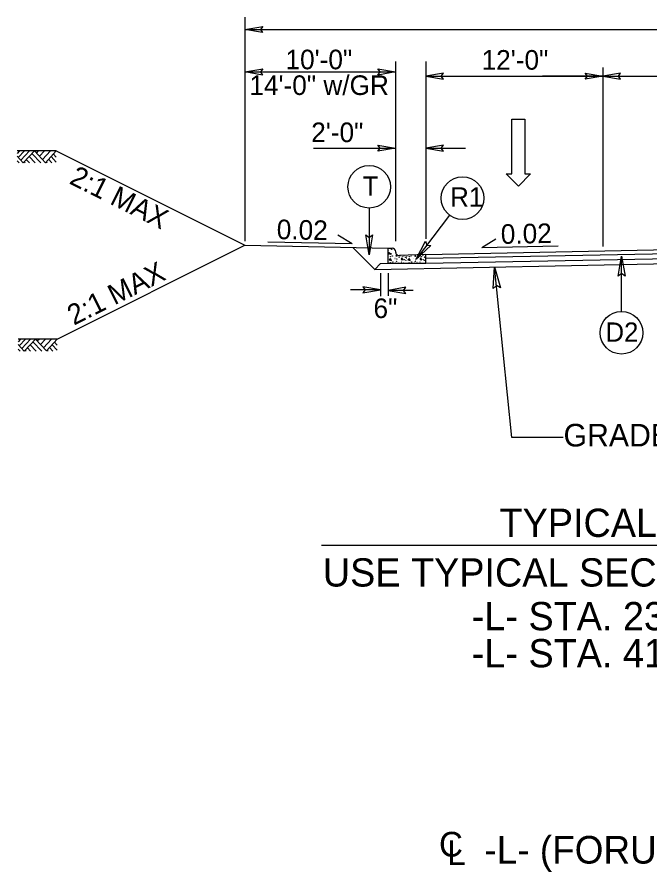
# Model space of a CAD drawing. Extents: x 1904401 to 1905163, y 193929 to 194736.
# Drawn here: x 1904864.8 to 1904906.8, y 194556.6 to 194613.3 of the extents above; entities that cross this region are included whole.
import ezdxf

# ---------------------------------------------------------------- set-up
doc = ezdxf.new("R2010")
doc.units = 0
for name, color, linetype in [('Default', 7, 'Continuous'), ('Old_Level_1', 7, 'Continuous'), ('Old_Level_11', 7, 'Continuous'), ('Old_Level_20', 7, 'Continuous'), ('Prop Dimension Text', 7, 'Continuous'), ('Prop Lane Arrow CELL', 7, 'Continuous'), ('Typical Arrow Superelevation CELL', 7, 'Continuous'), ('Typical Berm CELL', 7, 'Continuous'), ('Typical Curb CELL', 7, 'Continuous'), ('Typical Hinge Slope Arterial CELL', 7, 'Continuous'), ('Typical Pavement Slope CELL', 7, 'Continuous'), ('Typical Terminator CELL', 7, 'Continuous'), ('Typical Text Centerline CELL', 7, 'Continuous')]:
    doc.layers.add(name, color=color, linetype=linetype)

msp = doc.modelspace()

# ---------------------------------------------------------------- linework, layer by layer
at = {"layer": 'Default'}
msp.add_line((1904903.66, 194609.923), (1904903.66, 194598.051), dxfattribs=at)
at = {"layer": 'Old_Level_1'}
for p, q in [((1904879.91, 194612.433), (1904943.41, 194612.433)), ((1904879.91, 194609.62), (1904889.91, 194609.62)), ((1904891.91, 194609.34), (1904903.91, 194609.34)), ((1904903.66, 194609.34), (1904899.66, 194609.34)), ((1904903.66, 194609.34), (1904919.66, 194609.34)), ((1904864.96, 194604.388), (1904864.79, 194604.205)), ((1904865.28, 194604.388), (1904864.866, 194603.944)), ((1904865.613, 194604.388), (1904865.033, 194603.765)), ((1904865.935, 194604.387), (1904865.194, 194603.591)), ((1904866.356, 194603.583), (1904865.77, 194604.211)), ((1904866.666, 194603.601), (1904865.935, 194604.387)), ((1904866.199, 194604.388), (1904866.066, 194604.245)), ((1904866.601, 194604.388), (1904866.268, 194604.029)), ((1904866.999, 194604.388), (1904866.466, 194603.815)), ((1904867.39, 194604.38), (1904866.666, 194603.601)), ((1904867.39, 194603.979), (1904867.204, 194604.179)), ((1904884.463, 194604.574), (1904889.91, 194604.574)), ((1904891.91, 194604.574), (1904894.55, 194604.574)), ((1904865.194, 194603.591), (1904864.79, 194604.026)), ((1904864.924, 194603.583), (1904864.79, 194603.726)), ((1904865.325, 194603.583), (1904865.256, 194603.657)), ((1904865.62, 194603.583), (1904865.403, 194603.816)), ((1904865.986, 194603.583), (1904865.586, 194604.012)), ((1904866.791, 194603.583), (1904866.72, 194603.659)), ((1904867.102, 194603.583), (1904866.875, 194603.826)), ((1904867.39, 194603.646), (1904867.048, 194604.012)), ((1904865.027, 194591.902), (1904864.857, 194591.719)), ((1904865.347, 194591.902), (1904864.933, 194591.458)), ((1904865.68, 194591.902), (1904865.1, 194591.279)), ((1904866.002, 194591.901), (1904865.261, 194591.105)), ((1904866.423, 194591.097), (1904865.837, 194591.725)), ((1904866.733, 194591.115), (1904866.002, 194591.901)), ((1904866.266, 194591.902), (1904866.133, 194591.759)), ((1904866.668, 194591.902), (1904866.335, 194591.543)), ((1904867.066, 194591.902), (1904866.533, 194591.329)), ((1904867.457, 194591.894), (1904866.733, 194591.115)), ((1904867.457, 194591.493), (1904867.271, 194591.693)), ((1904865.261, 194591.105), (1904864.857, 194591.54)), ((1904864.991, 194591.097), (1904864.857, 194591.24)), ((1904865.392, 194591.097), (1904865.323, 194591.171)), ((1904865.687, 194591.097), (1904865.47, 194591.33)), ((1904866.053, 194591.097), (1904865.653, 194591.526)), ((1904866.858, 194591.097), (1904866.787, 194591.173)), ((1904867.169, 194591.097), (1904866.942, 194591.34)), ((1904867.457, 194591.16), (1904867.115, 194591.526)), ((1904884.997, 194578.236), (1904937.39, 194578.236))]:
    msp.add_line(p, q, dxfattribs=at)
for points in [[(1904867.39, 194604.388), (1904864.79, 194604.388)], [(1904867.457, 194591.902), (1904864.857, 194591.902)]]:
    msp.add_lwpolyline(points, dxfattribs=at)
at = {"layer": 'Old_Level_11'}
for p, q in [((1904888.156, 194600.592), (1904888.156, 194597.502)), ((1904893.491, 194600.123), (1904891.279, 194597.214)), ((1904904.897, 194593.739), (1904904.897, 194597.394))]:
    msp.add_line(p, q, dxfattribs=at)
for points in [[(1904888.381, 194598.811), (1904888.156, 194597.502), (1904887.923, 194598.818), (1904888.156, 194598.651)], [(1904892.251, 194598.12), (1904891.279, 194597.214), (1904891.891, 194598.403), (1904891.975, 194598.129)], [(1904904.672, 194596.084), (1904904.897, 194597.394), (1904905.13, 194596.077), (1904904.897, 194596.245)]]:
    msp.add_lwpolyline(points, close=True, dxfattribs=at)
for centre in [(1904888.156, 194602.006), (1904894.347, 194601.249), (1904904.897, 194592.325)]:
    msp.add_circle(centre, 1.414, dxfattribs=at)
at = {"layer": 'Prop Dimension Text'}
for p, q in [((1904879.91, 194613.26), (1904879.91, 194598.394)), ((1904889.91, 194610.313), (1904889.91, 194598.394)), ((1904891.91, 194610.313), (1904891.91, 194598.548)), ((1904892.66, 194609.34), (1904903.66, 194609.34))]:
    msp.add_line(p, q, dxfattribs=at)
at = {"layer": 'Prop Lane Arrow CELL'}
for p, q in [((1904897.622, 194606.491), (1904898.478, 194606.491)), ((1904897.622, 194602.86), (1904897.622, 194606.491)), ((1904898.478, 194606.491), (1904898.478, 194602.86)), ((1904898.063, 194602.043), (1904897.233, 194602.86)), ((1904897.233, 194602.86), (1904897.622, 194602.86)), ((1904898.867, 194602.86), (1904898.063, 194602.043)), ((1904898.478, 194602.86), (1904898.867, 194602.86)), ((1904888.91, 194596.28), (1904888.91, 194594.741)), ((1904889.41, 194596.279), (1904889.41, 194594.781)), ((1904897.616, 194585.387), (1904896.473, 194596.688)), ((1904888.91, 194595.163), (1904886.92, 194595.163)), ((1904891.082, 194595.135), (1904889.41, 194595.135)), ((1904901.015, 194585.387), (1904897.616, 194585.387))]:
    msp.add_line(p, q, dxfattribs=at)
at = {"layer": 'Typical Arrow Superelevation CELL'}
for p, q in [((1904887.016, 194598.225), (1904886.077, 194598.793)), ((1904895.625, 194597.978), (1904896.564, 194598.546)), ((1904887.016, 194598.225), (1904881.423, 194598.337)), ((1904895.625, 194597.978), (1904900.696, 194598.08))]:
    msp.add_line(p, q, dxfattribs=at)
at = {"layer": 'Typical Berm CELL'}
msp.add_line((1904879.91, 194598.128), (1904889.41, 194597.93), dxfattribs=at)
at = {"layer": 'Typical Curb CELL'}
for p, q in [((1904889.41, 194596.931), (1904889.41, 194597.93)), ((1904889.41, 194597.93), (1904889.671, 194597.93)), ((1904889.447, 194597.552), (1904889.601, 194597.597)), ((1904889.584, 194597.506), (1904889.447, 194597.552)), ((1904889.601, 194597.597), (1904889.584, 194597.506)), ((1904889.91, 194597.68), (1904889.91, 194597.691)), ((1904891.91, 194597.514), (1904890.16, 194597.441)), ((1904891.91, 194596.931), (1904891.91, 194597.514)), ((1904889.41, 194596.931), (1904891.91, 194596.931)), ((1904889.573, 194597.234), (1904889.47, 194597.159)), ((1904889.47, 194597.159), (1904889.635, 194597.119)), ((1904889.635, 194597.119), (1904889.573, 194597.234)), ((1904890.314, 194597.29), (1904890.28, 194597.176)), ((1904890.28, 194597.176), (1904890.4, 194597.17)), ((1904890.4, 194597.17), (1904890.314, 194597.29)), ((1904890.821, 194597.234), (1904890.718, 194597.159)), ((1904890.718, 194597.159), (1904890.884, 194597.119)), ((1904890.884, 194597.119), (1904890.821, 194597.234)), ((1904891.563, 194597.29), (1904891.529, 194597.176)), ((1904891.529, 194597.176), (1904891.649, 194597.17)), ((1904891.649, 194597.17), (1904891.563, 194597.29))]:
    msp.add_line(p, q, dxfattribs=at)
for centre in [(1904889.424, 194597.82), (1904889.475, 194597.638), (1904889.572, 194597.365), (1904889.64, 194597.855), (1904889.692, 194597.415), (1904889.949, 194597.444), (1904889.966, 194597.393), (1904890.171, 194597.409), (1904890.366, 194597.37), (1904890.463, 194597.424), (1904890.571, 194597.33), (1904890.627, 194597.365), (1904890.821, 194597.365), (1904890.941, 194597.415), (1904891.198, 194597.444), (1904891.215, 194597.393), (1904891.42, 194597.409), (1904891.569, 194597.472), (1904891.615, 194597.37), (1904891.712, 194597.455), (1904891.82, 194597.33), (1904891.876, 194597.365), (1904889.555, 194596.976), (1904889.726, 194597.016), (1904889.869, 194597.25), (1904889.903, 194596.954), (1904889.96, 194597.068), (1904889.994, 194597.222), (1904890.074, 194596.982), (1904890.143, 194597.308), (1904890.28, 194597.005), (1904890.44, 194596.937), (1904890.491, 194597.17), (1904890.587, 194597.125), (1904890.644, 194597.268), (1904890.65, 194596.959), (1904890.804, 194596.976), (1904890.975, 194597.016), (1904891.118, 194597.25), (1904891.152, 194596.954), (1904891.209, 194597.068), (1904891.243, 194597.222), (1904891.324, 194596.982), (1904891.392, 194597.308), (1904891.529, 194597.005), (1904891.689, 194596.937), (1904891.74, 194597.17), (1904891.836, 194597.125), (1904891.893, 194597.268), (1904891.899, 194596.959)]:
    msp.add_circle(centre, 0.00802, dxfattribs=at)
for centre, start, end in [((1904889.671, 194597.691), 0, 90), ((1904890.15, 194597.68), 180, 272.3845)]:
    msp.add_arc(centre, 0.24, start, end, dxfattribs=at)
at = {"layer": 'Typical Hinge Slope Arterial CELL'}
for p in [(1904867.39, 194604.388), (1904867.457, 194591.902)]:
    msp.add_line(p, (1904879.91, 194598.128), dxfattribs=at)
at = {"layer": 'Typical Pavement Slope CELL'}
for p, q in [((1904888.519, 194596.529), (1904887.069, 194597.979)), ((1904891.91, 194597.514), (1904911.66, 194597.909)), ((1904891.915, 194597.264), (1904911.665, 194597.659)), ((1904888.519, 194596.529), (1904911.678, 194596.992)), ((1904888.519, 194596.529), (1904888.91, 194596.921)), ((1904888.91, 194596.921), (1904889.41, 194596.931)), ((1904891.921, 194596.931), (1904911.671, 194597.326))]:
    msp.add_line(p, q, dxfattribs=at)
at = {"layer": 'Typical Terminator CELL'}
for points in [[(1904881.081, 194612.231), (1904879.91, 194612.433), (1904881.088, 194612.641), (1904880.938, 194612.433)], [(1904881.081, 194609.418), (1904879.91, 194609.62), (1904881.088, 194609.828), (1904880.938, 194609.62)], [(1904888.738, 194609.822), (1904889.91, 194609.62), (1904888.732, 194609.412), (1904888.881, 194609.62)], [(1904893.081, 194609.542), (1904891.91, 194609.34), (1904893.088, 194609.132), (1904892.938, 194609.34)], [(1904902.488, 194609.542), (1904903.66, 194609.34), (1904902.482, 194609.132), (1904902.631, 194609.34)], [(1904904.831, 194609.542), (1904903.66, 194609.34), (1904904.838, 194609.132), (1904904.688, 194609.34)], [(1904888.738, 194604.776), (1904889.91, 194604.574), (1904888.732, 194604.366), (1904888.881, 194604.574)], [(1904893.081, 194604.776), (1904891.91, 194604.574), (1904893.088, 194604.366), (1904892.938, 194604.574)], [(1904896.386, 194595.264), (1904896.473, 194596.688), (1904896.876, 194595.31), (1904896.608, 194595.461)], [(1904887.739, 194594.961), (1904888.91, 194595.163), (1904887.732, 194595.371), (1904887.882, 194595.163)], [(1904890.582, 194595.337), (1904889.41, 194595.135), (1904890.588, 194594.927), (1904890.439, 194595.135)]]:
    msp.add_lwpolyline(points, close=True, dxfattribs=at)

# ---------------------------------------------------------------- texts
at = {"layer": 'Old_Level_1'}
for s, height, p in [('10\'-0"', 1.3, (1904882.601, 194609.798)), ('12\'-0" ', 1.3, (1904895.613, 194609.772)), ('14\'-0" w/GR', 1.3, (1904880.204, 194608.094)), ('2\'-0" ', 1.3, (1904884.308, 194604.967)), ('6" ', 1.3, (1904888.44, 194593.3)), ('TYPICAL SECTION NO. 2', 1.875, (1904896.804, 194578.781))]:
    msp.add_text(s, height=height, dxfattribs=at).set_placement(p)
at = {"layer": 'Old_Level_20'}
for s, height, p in [('T', 1.279, (1904887.72, 194601.409)), ('R1', 1.2792, (1904893.531, 194600.69)), ('D2', 1.2792, (1904903.832, 194591.728))]:
    msp.add_text(s, height=height, dxfattribs=at).set_placement(p)
at = {"layer": 'Prop Dimension Text'}
for rotation, p in [(358.8538, (1904882.009, 194598.534)), (1.1462, (1904896.9, 194598.214))]:
    msp.add_text('0.02', height=1.3, rotation=rotation, dxfattribs=at).set_placement(p)
at = {"layer": 'Prop Lane Arrow CELL'}
msp.add_text('GRADE TO THIS LINE', height=1.5, rotation=0.0002, dxfattribs=at).set_placement((1904901.05, 194584.78))
for s, p in [('USE TYPICAL SECTION NO. 2', (1904885.076, 194575.491)), ('-L- STA. 23+64.39 TO 28+87.00', (1904894.962, 194572.591)), ('-L- STA. 41+82.00 TO 42+96.00', (1904894.962, 194570.133))]:
    msp.add_text(s, height=1.875, dxfattribs=at).set_placement(p)
at = {"layer": 'Typical Hinge Slope Arterial CELL'}
for rotation, p in [(333.435, (1904868.181, 194602.25)), (26.5651, (1904868.553, 194592.791))]:
    msp.add_text('2:1 MAX', height=1.35, rotation=rotation, dxfattribs=at).set_placement(p)
at = {"layer": 'Typical Text Centerline CELL'}
msp.add_text('C', height=1.64, dxfattribs=at).set_placement((1904892.788, 194557.58))
for s, height, rotation, p in [('-L- (FORUM PARKWAY)', 1.83231, 0, (1904895.803, 194557.115)), ('L', 1.641, 359.9469, (1904893.333, 194557.02))]:
    msp.add_text(s, height=height, rotation=rotation, dxfattribs=at).set_placement(p)

doc.saveas('drawing.dxf')
